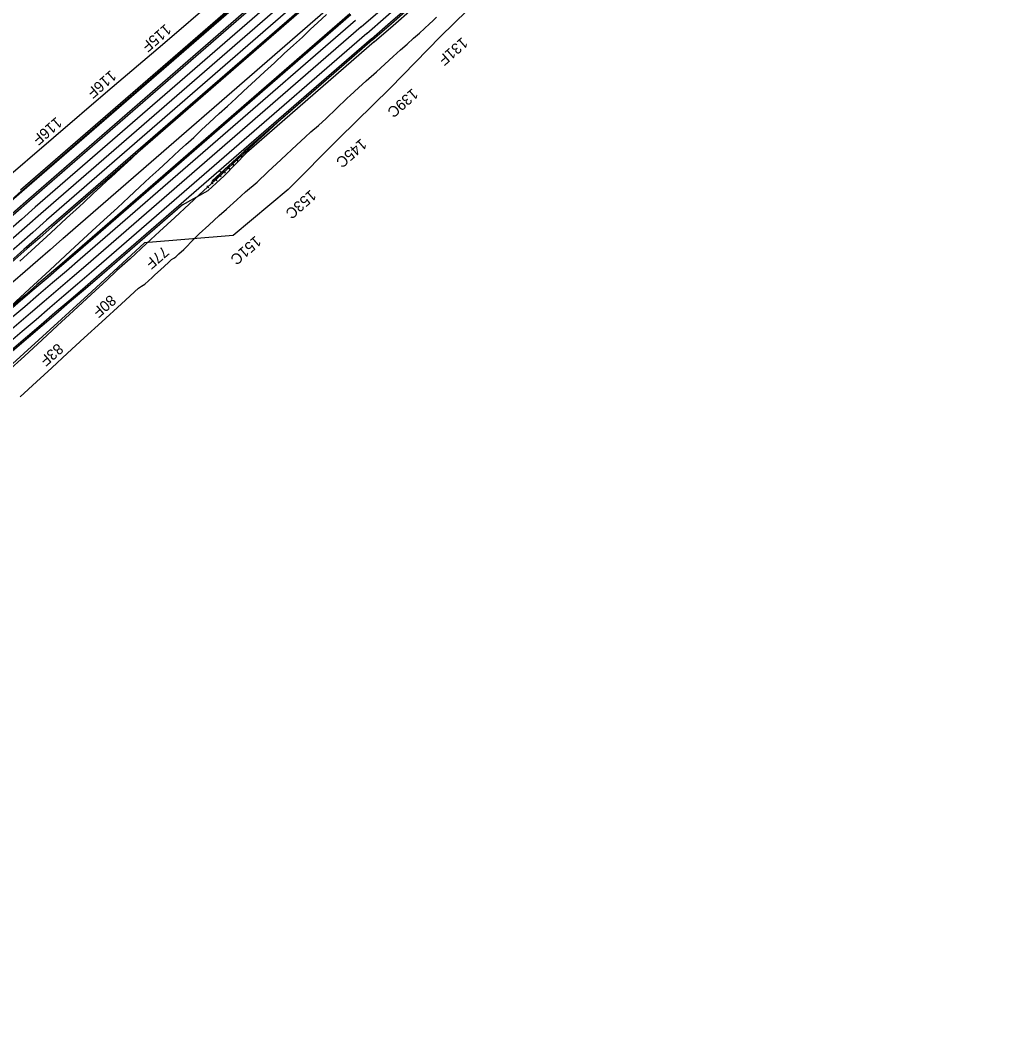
# Model space of a CAD drawing. Extents: x 2163396 to 2173129, y 605545 to 614595.
# Drawn here: x 2169556 to 2170912, y 610268 to 611691 of the extents above; entities that cross this region are included whole.
import ezdxf

# ---------------------------------------------------------------- set-up
doc = ezdxf.new("R2010")
doc.units = 0
for name, color, linetype in [('RD_PD_AsphRem', 7, 'Continuous'), ('RD_PD_CstnLmt', 7, 'Continuous'), ('RD_PD_EarthShd', 7, 'Continuous'), ('RD_PD_Final_LnLine', 7, 'Continuous'), ('RD_PD_Final_TrvlWay', 7, 'Continuous'), ('RD_PD_GR', 7, 'Continuous'), ('RD_PD_MedBWall', 7, 'Continuous'), ('RD_PD_TX_CstnLmt', 7, 'Continuous')]:
    doc.layers.add(name, color=color, linetype=linetype)

msp = doc.modelspace()

# ---------------------------------------------------------------- linework, layer by layer
at = {"layer": 'RD_PD_AsphRem'}
for points in [[(2169984, 611736.6), (2169723.7, 611510.7), (2169722.6, 611509.8)], [(2169543.2, 611293.5), (2169568.7, 611316.9), (2169597.1, 611343.3), (2169626.2, 611370.1), (2169643.9, 611386.4), (2169656.2, 611397.8), (2169672.4, 611412.6), (2169691.4, 611430.2), (2169707.3, 611444.8), (2169722.9, 611459.4), (2169736.7, 611472.1), (2169749.4, 611483.7), (2169762.1, 611495.7), (2169778, 611510.2), (2169786.9, 611518.1), (2169797.8, 611528.2), (2169808.9, 611538.7), (2169819.9, 611548.9), (2169833.2, 611561.4), (2169844.9, 611571.9), (2169856.9, 611583), (2169867.1, 611592.5), (2169884.2, 611608.1), (2169896.6, 611619.7), (2169910.3, 611632.4), (2169924, 611645.1), (2169937.2, 611656.9), (2169949.4, 611668.2), (2169960.8, 611679.2), (2169970.4, 611688.1), (2169983, 611699.5)], [(2169556, 611166.4), (2169578.6, 611187.4), (2169599.9, 611207.1), (2169622, 611227.4), (2169645.1, 611248.6), (2169669.7, 611271.2), (2169697, 611296.4), (2169720.8, 611318.2), (2169725, 611320.6), (2169729.7, 611323.7), (2169734.8, 611328.1), (2169739.7, 611332.7), (2169743.6, 611336.7), (2169751.7, 611343.7), (2169762.5, 611353.7), (2169766.7, 611358), (2169769.9, 611359.9), (2169772.7, 611361.6), (2169776.9, 611365.7), (2169783.9, 611372.1), (2169788.6, 611376.5), (2169794, 611382.1), (2169797.6, 611385.8), (2169805.3, 611393.7), (2169818.7, 611405.8), (2169833.5, 611419.4), (2169843.4, 611428.3), (2169857.8, 611441.1), (2169870.2, 611452.3), (2169886.1, 611466), (2169901.4, 611480.2), (2169919.6, 611497.2), (2169941.6, 611517.9), (2169953.2, 611528.6), (2169961.1, 611535.8), (2169971.7, 611544.7), (2169982.5, 611554.8), (2169997.1, 611568.7), (2170001.6, 611573.1), (2170006.5, 611577.8), (2170012, 611583), (2170015.9, 611586.8), (2170027.5, 611597.4), (2170038.2, 611607), (2170052.8, 611619.7), (2170064.4, 611630.4), (2170075.9, 611641), (2170086, 611650.1), (2170095.5, 611658.3), (2170104.5, 611666.5), (2170112.5, 611673.4), (2170126.5, 611686.4), (2170131.1, 611690.6), (2170136.4, 611696)], [(2170046.9, 611664.1), (2169921.4, 611555.2), (2169921.2, 611555)], [(2169921.2, 611555), (2169896.5, 611532.3), (2169882.3, 611519.2), (2169860.8, 611499.4), (2169837.9, 611478), (2169811.4, 611453.7), (2169791.5, 611435.3), (2169771.3, 611416.6), (2169750.1, 611397.1), (2169731.8, 611380.3), (2169709, 611358.8), (2169690.7, 611342.5), (2169676.8, 611329.3), (2169655, 611309.2), (2169630.4, 611286.4), (2169607.9, 611265.8), (2169586.6, 611246.1), (2169561.7, 611223.1), (2169538.4, 611201.7)], [(2169722.6, 611509.8), (2169710.6, 611498.5), (2169695.9, 611484.8), (2169682.5, 611472.6), (2169677.3, 611468.3), (2169668.2, 611459.7), (2169657.6, 611449.9), (2169644.4, 611437.6), (2169638.6, 611432.1), (2169620.4, 611415.8), (2169598.6, 611395.4), (2169576.6, 611375.3), (2169555.2, 611355.6)]]:
    msp.add_lwpolyline(points, dxfattribs=at)
msp.add_arc((2122152.2, 666851.2), 73072, 310.953509, 312.719474, dxfattribs=at)
at = {"layer": 'RD_PD_CstnLmt'}
for p, q in [((2170213.6, 611739), (2170141.8, 611668.9)), ((2169830.2, 611722.7), (2169754.5, 611657.3)), ((2170141.8, 611668.9), (2170071.7, 611596.9)), ((2169754.5, 611657.3), (2169678, 611592.9)), ((2170071.7, 611596.9), (2170000, 611526.9)), ((2169678, 611592.9), (2169602.2, 611527.6)), ((2169602.2, 611527.6), (2169526.2, 611462.6)), ((2170000, 611526.9), (2169929.6, 611455.5)), ((2169929.6, 611455.5), (2169852.8, 611391.4)), ((2169852.8, 611391.4), (2169729.1, 611381.4)), ((2169729.1, 611381.4), (2169655.6, 611313.6)), ((2169655.6, 611313.6), (2169582, 611246)), ((2169582, 611246), (2169508, 611178.9))]:
    msp.add_line(p, q, dxfattribs=at)
msp.add_lwpolyline([(2169556, 611166.4), (2169578.6, 611187.4), (2169599.9, 611207.1), (2169622, 611227.4), (2169645.1, 611248.6), (2169669.7, 611271.2), (2169697, 611296.4), (2169720.8, 611318.2), (2169725, 611320.6), (2169729.7, 611323.7), (2169734.8, 611328.1), (2169739.7, 611332.7), (2169743.6, 611336.7), (2169751.7, 611343.7), (2169762.5, 611353.7), (2169766.7, 611358), (2169769.9, 611359.9), (2169772.7, 611361.6), (2169776.9, 611365.7), (2169783.9, 611372.1), (2169788.6, 611376.5), (2169794, 611382.1), (2169798.8, 611387.1)], dxfattribs=at)
at = {"layer": 'RD_PD_EarthShd'}
for p, q in [((2169939.9, 611787.5), (2169556.2, 611454.5)), ((2169984, 611736.6), (2169600.3, 611403.7)), ((2170015.5, 611700.4), (2169631.8, 611367.4)), ((2170049.4, 611661.3), (2169871.5, 611506.9)), ((2169840.2, 611474.5), (2169871.5, 611506.9)), ((2169840.2, 611474.5), (2169818.2, 611454.2)), ((2169782.2, 611434.4), (2169818.2, 611454.2)), ((2169782.2, 611434.4), (2169663.2, 611331.1))]:
    msp.add_line(p, q, dxfattribs=at)
for centre, radius, start, end in [((2122152.2, 666851.2), 73075.8, 310.953509, 312.719474), ((2217890.3, 556637.7), 73015.3, 131.404285, 132.56198), ((2217031.5, 555875.3), 72980.2, 130.502969, 131.661178), ((2217031.5, 555875.3), 72932.2, 130.502672, 131.772193)]:
    msp.add_arc(centre, radius, start, end, dxfattribs=at)
at = {"layer": 'RD_PD_Final_LnLine'}
for p, q in [((2169941.8, 611785.2), (2169558.2, 611452.2)), ((2169951, 611774.7), (2169567.3, 611441.7)), ((2169960.4, 611763.8), (2169576.7, 611430.8)), ((2169968.3, 611754.8), (2169584.6, 611421.8)), ((2169976.2, 611745.7), (2169592.5, 611412.7)), ((2170023.3, 611691.3), (2169639.7, 611358.3)), ((2170031.2, 611682.3), (2169647.5, 611349.3)), ((2170039.1, 611673.2), (2169655.4, 611340.2))]:
    msp.add_line(p, q, dxfattribs=at)
for centre, radius, start, end in [((2122152.2, 666851.2), 73048, 310.953509, 312.719474), ((2122152.2, 666851.2), 73060, 310.953509, 312.719474), ((2217890.3, 556637.7), 73079.7, 131.403889, 132.673453), ((2217890.3, 556637.7), 73065.7, 131.403889, 132.673536), ((2217890.3, 556637.7), 73051.3, 131.404063, 132.684686), ((2217890.3, 556637.7), 73039.3, 131.404137, 132.684757), ((2217890.3, 556637.7), 73027.3, 131.404211, 132.684829), ((2217031.5, 555875.3), 72968.2, 130.502895, 131.783502), ((2217031.5, 555875.3), 72956.2, 130.502821, 131.783426), ((2217031.5, 555875.3), 72944.2, 130.502746, 131.783349)]:
    msp.add_arc(centre, radius, start, end, dxfattribs=at)
at = {"layer": 'RD_PD_Final_TrvlWay'}
for p, q in [((2169941.2, 611786), (2169557.5, 611453)), ((2169982.7, 611738.2), (2169599, 611405.2)), ((2170016.8, 611698.9), (2169633.1, 611365.9)), ((2170045.6, 611665.7), (2169661.9, 611332.7))]:
    msp.add_line(p, q, dxfattribs=at)
for centre, radius, start, end in [((2122152.2, 666851.2), 73070, 310.953509, 312.719474), ((2217890.3, 556637.7), 73080.7, 131.403882, 132.673447), ((2217890.3, 556637.7), 73017.3, 131.404285, 132.673836), ((2217031.5, 555875.3), 72978.2, 130.502969, 131.772513), ((2217031.5, 555875.3), 72934.2, 130.502672, 131.772206)]:
    msp.add_arc(centre, radius, start, end, dxfattribs=at)
at = {"layer": 'RD_PD_GR'}
for p, q in [((2169998.8, 611719.7), (2169615.1, 611386.7)), ((2170046.9, 611664.1), (2169869, 611509.7)), ((2169869, 611509.7), (2169823.5, 611467.6)), ((2169824.6, 611467.9), (2169869.3, 611509.3)), ((2169856.3, 611497.3), (2169857.6, 611498.5)), ((2169857.7, 611495.8), (2169856.3, 611497.3)), ((2169857.6, 611498.5), (2169858.9, 611497)), ((2169858.9, 611497), (2169857.7, 611495.8)), ((2169858.3, 611496.4), (2169859.2, 611495.5)), ((2169858.5, 611494.9), (2169859.8, 611496.1)), ((2169862.2, 611502.7), (2169863.5, 611503.9)), ((2169863.5, 611501.2), (2169862.2, 611502.7)), ((2169863.5, 611503.9), (2169864.8, 611502.4)), ((2169864.8, 611502.4), (2169863.5, 611501.2)), ((2169864.2, 611501.8), (2169865, 611500.9)), ((2169864.4, 611500.3), (2169865.7, 611501.5)), ((2169868, 611508.1), (2169869.3, 611509.3)), ((2169869.4, 611506.7), (2169868, 611508.1)), ((2169869.3, 611509.3), (2169869, 611509.7)), ((2169869.3, 611509.3), (2169870.7, 611507.9)), ((2169870.7, 611507.9), (2169869.4, 611506.7)), ((2169870, 611507.3), (2169870.9, 611506.4)), ((2169870.3, 611505.8), (2169871.5, 611507)), ((2169833.4, 611481.9), (2169836, 611479.1)), ((2169838.7, 611481), (2169840, 611482.2)), ((2169840, 611482.2), (2169841.3, 611480.7)), ((2169844.6, 611486.4), (2169845.9, 611487.6)), ((2169845.9, 611484.9), (2169844.6, 611486.4)), ((2169845.9, 611487.6), (2169847.2, 611486.1)), ((2169847.2, 611486.1), (2169845.9, 611484.9)), ((2169846.6, 611485.5), (2169847.4, 611484.6)), ((2169846.8, 611484), (2169848.1, 611485.2)), ((2169850.4, 611491.8), (2169851.7, 611493)), ((2169851.8, 611490.4), (2169850.4, 611491.8)), ((2169851.7, 611493), (2169853.1, 611491.6)), ((2169853.1, 611491.6), (2169851.8, 611490.4)), ((2169852.4, 611491), (2169853.3, 611490.1)), ((2169852.6, 611489.5), (2169853.9, 611490.6)), ((2169823.5, 611467.6), (2169824.2, 611466.8)), ((2169824.2, 611466.8), (2169824.9, 611467.5)), ((2169824.9, 611467.5), (2169824.6, 611467.9)), ((2169827, 611470.1), (2169828.2, 611471.3)), ((2169828.3, 611468.6), (2169827, 611470.1)), ((2169828.2, 611471.3), (2169829.6, 611469.8)), ((2169829.6, 611469.8), (2169828.3, 611468.6)), ((2169829, 611469.2), (2169829.8, 611468.3)), ((2169829.2, 611467.7), (2169830.4, 611468.9)), ((2169832.8, 611475.5), (2169834.1, 611476.7)), ((2169834.2, 611474.1), (2169832.8, 611475.5)), ((2169834.1, 611476.7), (2169835.5, 611475.3)), ((2169835.5, 611475.3), (2169834.2, 611474.1)), ((2169834.8, 611474.7), (2169835.7, 611473.7)), ((2169835, 611473.1), (2169836.3, 611474.3)), ((2169840.1, 611479.5), (2169838.7, 611481)), ((2169841.3, 611480.7), (2169840.1, 611479.5)), ((2169840.7, 611480.1), (2169841.5, 611479.2)), ((2169840.9, 611478.6), (2169842.2, 611479.8)), ((2169816.2, 611460.8), (2169818.7, 611458)), ((2169822, 611466.2), (2169824.6, 611463.5))]:
    msp.add_line(p, q, dxfattribs=at)
for centre, radius, start, end in [((2122152.2, 666851.2), 73072, 310.953509, 312.719474), ((2217463.6, 556252.9), 73001.5, 130.953509, 132.108774)]:
    msp.add_arc(centre, radius, start, end, dxfattribs=at)
at = {"layer": 'RD_PD_MedBWall'}
for p, q in [((2169951, 611774.7), (2169567.3, 611441.7)), ((2169952.6, 611772.9), (2169568.9, 611439.9))]:
    msp.add_line(p, q, dxfattribs=at)
for radius, start, end in [(73065.7, 131.403975, 132.673536), (73063.3, 131.404063, 132.67355)]:
    msp.add_arc((2217890.3, 556637.7), radius, start, end, dxfattribs=at)

# ---------------------------------------------------------------- texts
at = {"layer": 'RD_PD_TX_CstnLmt'}
for s, rotation, p in [('115F', 220.9535, (2169758.5, 611687.3)), ('131F', 221.0121, (2170172, 611668.7)), ('116F', 220.9535, (2169682, 611622.8)), ('139C', 220.9535, (2170102.8, 611597.4)), ('116F', 220.9535, (2169606.2, 611557.6)), ('145C', 220.9535, (2170031.1, 611527.4)), ('153C', 220.9535, (2169960.7, 611456)), ('151C', 220.9535, (2169883.9, 611391.9)), ('77F', 220.9535, (2169755.1, 611377.4)), ('80F', 220.9671, (2169681.5, 611309.7)), ('83F', 221.0456, (2169607.9, 611242.1))]:
    msp.add_text(s, height=15, rotation=rotation, dxfattribs=at).set_placement(p)

doc.saveas('drawing.dxf')
